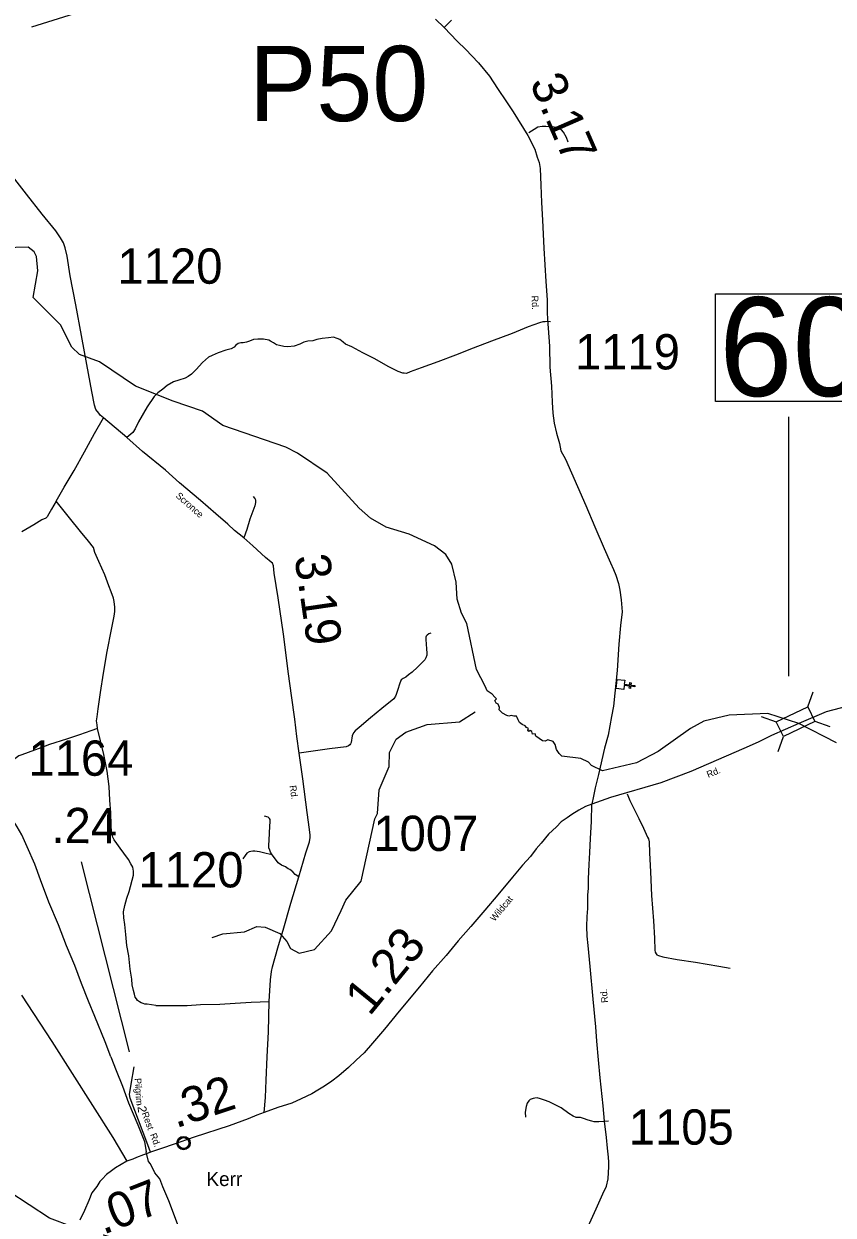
# Model space of a CAD drawing. Extents: x 2093524 to 2270757, y 289120 to 570408.
# Drawn here: x 2214080 to 2225547, y 329610 to 346501 of the extents above; entities that cross this region are included whole.
import ezdxf

# ---------------------------------------------------------------- set-up
doc = ezdxf.new("R2010")
doc.units = 0
for name, color, linetype in [('Exist Civil Demographics Community CELL', 7, 'Continuous'), ('Exist Civil Demographics Community Label', 7, 'Continuous'), ('Exist Cultural Church CELL', 7, 'Continuous'), ('Exist Hydrographic Creek Single Shore', 7, 'Continuous'), ('Exist Hydrographic Misc Water Feature', 7, 'Continuous'), ('Exist Road Non-System Type 51', 7, 'Continuous'), ('Exist Road Secondary Mileage Hundredths English Label', 7, 'Continuous'), ('Exist Road Secondary Structure Pipe Number Label', 7, 'Continuous'), ('Exist Road Secondary Structure Standard Bridge CELL', 7, 'Continuous'), ('Exist Road Secondary Structure Standard Bridge Number Label', 7, 'Continuous'), ('Exist Road Secondary Type 51 Attributed', 7, 'Continuous'), ('Exist Road Secondary Type 51 Label', 7, 'Continuous'), ('Exist Road Secondary Type 51 Number Label', 7, 'Continuous'), ('Exist Utilities Telephone Line', 7, 'Continuous')]:
    doc.layers.add(name, color=color, linetype=linetype)

msp = doc.modelspace()

# ---------------------------------------------------------------- linework, layer by layer
at = {"layer": 'Exist Civil Demographics Community CELL'}
msp.add_lwpolyline([(2216302, 330567), (2216297, 330570), (2216292, 330574), (2216286, 330579), (2216282, 330584), (2216278, 330590), (2216275, 330595), (2216272, 330600), (2216270, 330606), (2216268, 330613), (2216267, 330620), (2216266, 330625), (2216265, 330631), (2216266, 330637), (2216266, 330643), (2216267, 330647), (2216268, 330652), (2216269, 330656), (2216271, 330662), (2216273, 330666), (2216275, 330671), (2216278, 330675), (2216281, 330679), (2216284, 330684), (2216288, 330688), (2216293, 330693), (2216299, 330697), (2216304, 330700), (2216310, 330703), (2216314, 330705), (2216320, 330707), (2216325, 330709), (2216331, 330710), (2216337, 330711), (2216342, 330711), (2216348, 330711), (2216353, 330711), (2216358, 330710), (2216364, 330709), (2216368, 330707), (2216374, 330705), (2216379, 330703), (2216384, 330700), (2216389, 330697), (2216394, 330693), (2216399, 330689), (2216402, 330685), (2216407, 330680), (2216410, 330675), (2216413, 330670), (2216416, 330664), (2216418, 330657), (2216420, 330651), (2216421, 330645), (2216422, 330640), (2216422, 330632), (2216422, 330625), (2216421, 330619), (2216420, 330612), (2216418, 330608), (2216417, 330604), (2216415, 330599), (2216413, 330595), (2216410, 330590), (2216406, 330585), (2216403, 330581), (2216400, 330577), (2216396, 330574), (2216392, 330571), (2216386, 330566), (2216380, 330563), (2216374, 330560), (2216368, 330558), (2216363, 330557), (2216358, 330555), (2216349, 330554), (2216346, 330554), (2216341, 330554), (2216333, 330555), (2216326, 330556), (2216321, 330558), (2216315, 330560), (2216310, 330562), (2216305, 330565)], close=True, dxfattribs=at)
for radius in [94.3, 76.7]:
    msp.add_circle((2216343, 330633), radius, dxfattribs=at)
at = {"layer": 'Exist Cultural Church CELL'}
msp.add_lwpolyline([(2222595, 337194), (2222588, 337137), (2222664, 337128), (2222668, 337160), (2222683, 337158), (2222680, 337126), (2222739, 337119), (2222737, 337103), (2222678, 337110), (2222674, 337079), (2222658, 337081), (2222662, 337112), (2222586, 337121), (2222579, 337064), (2222474, 337077), (2222489, 337206)], close=True, dxfattribs=at)
at = {"layer": 'Exist Hydrographic Creek Single Shore'}
for points in [[(2214140, 343335), (2213965, 343332), (2213807, 343290), (2213541, 343157)], [(2220815, 336777), (2220821, 336808), (2220799, 336857), (2220771, 336868), (2220755, 336908), (2220775, 336932), (2220755, 336952), (2220715, 336998), (2220646, 337043), (2220615, 337109), (2220495, 337348), (2220358, 337997), (2220282, 338146), (2220222, 338344), (2220204, 338587), (2220144, 338838), (2220059, 338977), (2219900, 339102), (2219541, 339266), (2219215, 339364), (2218990, 339494), (2218830, 339634), (2218377, 340132), (2217959, 340413), (2217791, 340501), (2216898, 340804), (2216613, 341010), (2216196, 341149), (2215661, 341363), (2215151, 341708), (2214867, 341815), (2214758, 341916), (2214598, 342231), (2214212, 342619), (2214276, 343001), (2214258, 343202), (2214224, 343268), (2214140, 343335)], [(2222279, 335912), (2222125, 335987), (2222079, 336032), (2221974, 336087), (2221702, 336118), (2221664, 336158), (2221627, 336213), (2221607, 336282), (2221582, 336327), (2221504, 336349), (2221467, 336329), (2221427, 336333), (2221334, 336400), (2221323, 336433), (2221289, 336429), (2221278, 336468), (2221254, 336484), (2221234, 336468), (2221223, 336488), (2221232, 336508), (2221203, 336524), (2221183, 336548), (2221143, 336568), (2221103, 336593), (2221083, 336633), (2221072, 336664), (2221059, 336684), (2221023, 336684), (2220983, 336695), (2220953, 336684), (2220923, 336693), (2220862, 336728), (2220815, 336777)], [(2224623, 336725), (2224073, 336697), (2223716, 336612), (2223525, 336511), (2223069, 336182), (2222762, 336021), (2222279, 335912)], [(2225594, 336309), (2225059, 336582), (2224623, 336725)]]:
    msp.add_lwpolyline(points, dxfattribs=at)
at = {"layer": 'Exist Hydrographic Misc Water Feature'}
for points in [[(2214194, 346460), (2215099, 346741), (2215481, 346986), (2215664, 347045)], [(2216748, 333548), (2216898, 333598), (2217206, 333628), (2217380, 333703), (2217497, 333694), (2217706, 333605), (2217806, 333488), (2217857, 333389), (2217983, 333324), (2218199, 333375), (2218438, 333643), (2218578, 333929), (2218644, 334078), (2218858, 334346), (2219052, 335231), (2219093, 335306), (2219116, 335640), (2219255, 335972), (2219262, 336172), (2219353, 336357), (2219494, 336459), (2219793, 336568), (2220251, 336605), (2220475, 336748)], [(2215806, 328817), (2215404, 329242), (2215278, 329307), (2214769, 329445), (2214443, 329566), (2213866, 329948), (2213640, 330054), (2213356, 330250), (2213020, 330608), (2212694, 330745), (2212560, 330853), (2212375, 331184), (2212366, 331260), (2212230, 331584), (2212155, 331684), (2211611, 331954)]]:
    msp.add_lwpolyline(points, dxfattribs=at)
at = {"layer": 'Exist Road Non-System Type 51'}
for points in [[(2220139, 346555), (2220035, 346451)], [(2221794, 344823), (2221768, 344888), (2221725, 344964), (2221699, 344996), (2221667, 345018), (2221627, 345031), (2221559, 345041), (2221477, 345046), (2221423, 345046), (2221363, 345036), (2221311, 345005), (2221236, 344955)], [(2221544, 342274), (2221496, 342282), (2221468, 342277), (2221432, 342277), (2221386, 342261), (2221227, 342204), (2220999, 342112), (2220708, 342002), (2220447, 341903), (2220194, 341803), (2219947, 341711), (2219709, 341623), (2219556, 341566), (2219504, 341544), (2219468, 341546), (2219448, 341548), (2219384, 341573), (2219241, 341642), (2219051, 341749), (2218884, 341838), (2218726, 341919), (2218639, 341958), (2218603, 341988), (2218557, 342027), (2218517, 342041), (2218467, 342057), (2218397, 342050), (2218305, 342038), (2218233, 342023), (2218173, 342005), (2218105, 342002), (2218048, 341986), (2217988, 341957), (2217908, 341933), (2217820, 341922), (2217762, 341924), (2217700, 341939), (2217658, 341949), (2217616, 341977), (2217576, 342003), (2217550, 342018), (2217474, 342028), (2217397, 342031), (2217333, 342023), (2217276, 342000), (2217236, 341986), (2217186, 341976), (2217154, 341978), (2217118, 341967), (2217082, 341943), (2217060, 341917), (2217019, 341895), (2216943, 341874), (2216835, 341836), (2216747, 341797), (2216697, 341773), (2216612, 341700), (2216523, 341601), (2216455, 341533), (2216410, 341499), (2216366, 341479), (2216278, 341450), (2216198, 341425), (2216109, 341375), (2216049, 341322), (2215977, 341268), (2215926, 341218), (2215829, 341069), (2215704, 340858), (2215657, 340760), (2215623, 340706), (2215540, 340637)], [(2214538, 339732), (2214651, 339931), (2214793, 340170), (2214939, 340435), (2215083, 340694), (2215208, 340917)], [(2214538, 339732), (2214471, 339622), (2214434, 339552), (2214408, 339512), (2214390, 339492), (2214336, 339467), (2214221, 339398), (2214050, 339299)], [(2215124, 336510), (2215118, 336564), (2215108, 336620), (2215117, 336676), (2215132, 336790), (2215165, 337022), (2215207, 337294), (2215259, 337602), (2215323, 337916), (2215361, 338105), (2215367, 338167), (2215368, 338229), (2215358, 338311), (2215348, 338356), (2215315, 338448), (2215286, 338534), (2215225, 338688), (2215142, 338877), (2215087, 339005), (2215067, 339074), (2214998, 339166), (2214883, 339303), (2214726, 339496), (2214538, 339732)], [(2217327, 339798), (2217347, 339778), (2217357, 339764), (2217363, 339744), (2217363, 339714), (2217354, 339668), (2217283, 339476), (2217238, 339331), (2217195, 339213)], [(2219847, 337864), (2219817, 337854), (2219795, 337833), (2219782, 337821), (2219775, 337807), (2219776, 337769), (2219782, 337711), (2219787, 337633), (2219789, 337583), (2219789, 337550), (2219776, 337513), (2219760, 337485), (2219726, 337447), (2219658, 337381), (2219581, 337310), (2219529, 337270), (2219493, 337239), (2219456, 337217), (2219428, 337199), (2219406, 337153), (2219373, 337051), (2219357, 336993), (2219348, 336969), (2219320, 336932), (2219151, 336795), (2218990, 336660), (2218831, 336523), (2218775, 336479), (2218751, 336451), (2218732, 336407), (2218718, 336311), (2218710, 336295), (2218700, 336278), (2218679, 336262), (2218647, 336252), (2218411, 336220), (2217982, 336162)], [(2215124, 336510), (2215027, 336475), (2214867, 336420), (2214684, 336359), (2214442, 336281), (2214283, 336224), (2214141, 336171), (2214049, 336138), (2214007, 336124), (2213910, 336046), (2213872, 336019), (2213781, 335965), (2213669, 335910)], [(2215951, 332585), (2215887, 332590), (2215829, 332600), (2215795, 332604), (2215769, 332612), (2215743, 332621), (2215717, 332633), (2215691, 332653), (2215678, 332679), (2215656, 332703), (2215646, 332745), (2215632, 332797), (2215615, 332878), (2215611, 332958), (2215586, 333098), (2215566, 333286), (2215541, 333434), (2215524, 333591), (2215509, 333733), (2215497, 333825), (2215492, 333909), (2215512, 334001), (2215541, 334105), (2215572, 334198), (2215632, 334432), (2215634, 334486), (2215624, 334544), (2215597, 334590), (2215563, 334653), (2215498, 334741), (2215446, 334815), (2215397, 334882), (2215359, 334930), (2215339, 334970), (2215322, 335046), (2215316, 335138), (2215313, 335315), (2215297, 335495), (2215288, 335687), (2215258, 335905), (2215215, 336143), (2215166, 336334), (2215124, 336510)], [(2222628, 335582), (2222666, 335488), (2222727, 335368), (2222794, 335233), (2222861, 335099), (2222899, 335014), (2222918, 334970), (2222930, 334944), (2222938, 334902), (2222945, 334746), (2222959, 334478), (2222975, 334141), (2223000, 333783), (2223016, 333537), (2223021, 333367), (2223027, 333339), (2223041, 333315), (2223051, 333301), (2223073, 333290), (2223135, 333272), (2223338, 333237), (2223598, 333195), (2223928, 333142), (2224088, 333111)], [(2217598, 334721), (2217577, 334757), (2217563, 334787), (2217553, 334817), (2217553, 334859), (2217554, 334923), (2217560, 335029), (2217565, 335123), (2217570, 335191), (2217570, 335219), (2217562, 335235), (2217540, 335251), (2217488, 335269)], [(2217598, 334721), (2217512, 334737), (2217419, 334760), (2217351, 334772), (2217325, 334773), (2217297, 334767), (2217274, 334761), (2217238, 334743), (2217214, 334711), (2217182, 334660)], [(2217974, 334408), (2217925, 334440), (2217891, 334476), (2217849, 334509), (2217827, 334521), (2217789, 334549), (2217731, 334574), (2217684, 334604), (2217646, 334658), (2217598, 334721)], [(2215951, 332585), (2216041, 332585), (2216211, 332582), (2216393, 332584), (2216585, 332595), (2216857, 332603), (2217072, 332614), (2217302, 332630), (2217558, 332640)], [(2222362, 330944), (2222292, 330939), (2222228, 330935), (2222184, 330932), (2222160, 330934), (2222130, 330942), (2222078, 330958), (2222012, 330981), (2221967, 330995), (2221948, 330997), (2221906, 330996), (2221865, 331012), (2221801, 331050), (2221695, 331131), (2221616, 331172), (2221522, 331218), (2221456, 331243), (2221402, 331261), (2221354, 331275), (2221320, 331270), (2221296, 331264), (2221256, 331248), (2221236, 331232), (2221212, 331200), (2221199, 331151), (2221185, 331071), (2221188, 330998)]]:
    msp.add_lwpolyline(points, dxfattribs=at)
at = {"layer": 'Exist Road Secondary Structure Standard Bridge CELL'}
for p, q in [((2225189, 336818), (2225264, 337031)), ((2224528, 336679), (2224742, 336604)), ((2225287, 336614), (2225501, 336539)), ((2224767, 336182), (2224842, 336395))]:
    msp.add_line(p, q, dxfattribs=at)
msp.add_lwpolyline([(2224742, 336604), (2225189, 336819), (2225289, 336610), (2224842, 336395)], close=True, dxfattribs=at)
at = {"layer": 'Exist Road Secondary Structure Standard Bridge Number Label'}
msp.add_line((2224920, 337254), (2224920, 340931), dxfattribs=at)
msp.add_lwpolyline([(2223881, 342674), (2226458, 342674), (2226458, 341145), (2223881, 341145)], close=True, dxfattribs=at)
at = {"layer": 'Exist Road Secondary Type 51 Attributed'}
for points in [[(2219915, 346568), (2220035, 346451), (2220219, 346256), (2220342, 346136), (2220427, 346047), (2220520, 345947), (2220677, 345761), (2220793, 345586), (2220917, 345395), (2221014, 345251), (2221223, 344919), (2221320, 344724), (2221354, 344610), (2221380, 344535), (2221394, 344448), (2221405, 344214), (2221414, 343969), (2221431, 343719), (2221447, 343318), (2221476, 342848), (2221494, 342588), (2221493, 342408), (2221502, 342315), (2221527, 341930), (2221531, 341635), (2221555, 341364), (2221567, 341136), (2221573, 340979), (2221593, 340839), (2221626, 340695), (2221668, 340553), (2221689, 340449), (2221755, 340329), (2221926, 339939), (2222041, 339673), (2222170, 339367), (2222301, 339063), (2222394, 338857), (2222436, 338766), (2222467, 338686), (2222507, 338566), (2222524, 338471), (2222544, 338336), (2222556, 338165), (2222533, 337970), (2222509, 337704), (2222485, 337331), (2222454, 337010), (2222433, 336828), (2222407, 336679), (2222358, 336417), (2222307, 336229), (2222223, 335856), (2222176, 335667), (2222151, 335551), (2222130, 335435)], [(2217486, 331064), (2217503, 331280), (2217512, 331526), (2217527, 331854), (2217547, 332208), (2217558, 332640), (2217576, 332948), (2217587, 333066), (2217605, 333132), (2217636, 333250), (2217688, 333435), (2217753, 333651), (2217864, 334034), (2217974, 334408), (2218075, 334745), (2218126, 334901), (2218136, 334965), (2218135, 334999), (2218125, 335077), (2218093, 335321), (2218034, 335796), (2217982, 336162), (2217950, 336397), (2217920, 336641), (2217874, 336979), (2217830, 337286), (2217758, 337847), (2217683, 338365), (2217626, 338712), (2217618, 338818), (2217603, 338852), (2217583, 338868), (2217505, 338933), (2217324, 339098), (2217195, 339213), (2217066, 339316), (2216968, 339407), (2216801, 339552), (2216582, 339745), (2216286, 339994), (2216085, 340173), (2215763, 340439), (2215540, 340637), (2215208, 340917), (2215162, 340954), (2215140, 340982), (2215099, 341032), (2215079, 341096), (2215043, 341289), (2214971, 341671), (2214896, 342084), (2214817, 342517), (2214738, 342927), (2214693, 343206), (2214666, 343326), (2214643, 343396), (2214601, 343466), (2214532, 343565), (2214337, 343802), (2214115, 344086), (2213852, 344424)], [(2230785, 337533), (2230560, 337489), (2230207, 337437), (2229725, 337437), (2229443, 337474), (2228390, 337508), (2228268, 337491), (2227458, 337285), (2226095, 336925), (2225843, 336850), (2225450, 336747), (2225059, 336582)], [(2225059, 336582), (2224676, 336413), (2224483, 336318), (2224281, 336227), (2223531, 335900), (2223104, 335739), (2222391, 335532), (2222130, 335435)], [(2222130, 335435), (2222039, 335403), (2221945, 335352), (2221844, 335291), (2221776, 335244), (2221695, 335186), (2221625, 335115), (2221516, 335010), (2221410, 334883), (2221337, 334802), (2221258, 334695), (2221145, 334574), (2221004, 334403), (2220794, 334154), (2220613, 333936), (2220413, 333705), (2220235, 333501), (2220063, 333291), (2219872, 333074), (2219684, 332848), (2219396, 332501), (2219192, 332246), (2219022, 332051), (2218900, 331913), (2218787, 331810), (2218679, 331705), (2218542, 331585), (2218444, 331508), (2218340, 331439), (2218246, 331382), (2218159, 331330), (2218007, 331258), (2217879, 331200), (2217677, 331135), (2217486, 331064)], [(2222073, 329440), (2222189, 329699), (2222286, 329911), (2222335, 330021), (2222358, 330125), (2222362, 330216), (2222368, 330297), (2222368, 330361), (2222364, 330432), (2222350, 330560), (2222336, 330712), (2222308, 330942), (2222289, 331161), (2222248, 331559), (2222224, 331812), (2222199, 332076), (2222184, 332281), (2222148, 332673), (2222103, 333134), (2222074, 333435), (2222060, 333567), (2222055, 333701), (2222061, 333843), (2222071, 333957), (2222073, 334153), (2222079, 334242), (2222082, 334377), (2222090, 334582), (2222098, 334750), (2222107, 334950), (2222125, 335191), (2222130, 335435)], [(2214045, 332729), (2214475, 332071), (2215340, 330711), (2215541, 330376)], [(2215875, 330503), (2215836, 330606), (2215769, 330780), (2215586, 331268), (2215576, 331320), (2215599, 331469), (2215643, 331714)], [(2217486, 331064), (2217383, 331027), (2217258, 330978), (2216989, 330879), (2216494, 330714), (2216195, 330612), (2216044, 330560), (2215875, 330503)], [(2215875, 330503), (2215843, 330489), (2215774, 330466), (2215675, 330427), (2215623, 330404), (2215541, 330376)], [(2215541, 330376), (2215379, 330282), (2215322, 330240), (2215253, 330185), (2215190, 330121), (2215156, 330089), (2215116, 330015), (2215041, 329926), (2215002, 329817), (2214938, 329678), (2214873, 329540)]]:
    msp.add_lwpolyline(points, dxfattribs=at)
at = {"layer": 'Exist Road Secondary Type 51 Number Label'}
msp.add_line((2215578, 331925), (2214895, 334621), dxfattribs=at)
at = {"layer": 'Exist Utilities Telephone Line'}
for points in [[(2215312, 331853), (2215233, 332068), (2215084, 332425), (2214995, 332642), (2214897, 332897), (2214802, 333149), (2214684, 333430), (2214570, 333725), (2214434, 334050), (2214316, 334363), (2214234, 334588), (2214126, 334831), (2214049, 335001), (2213984, 335116), (2213891, 335266), (2213766, 335449), (2213589, 335671), (2213391, 335930), (2213161, 336240), (2212953, 336513), (2212729, 336785), (2212520, 337071), (2212310, 337334), (2212074, 337638)], [(2215312, 331853), (2215388, 331663), (2215479, 331438), (2215563, 331203), (2215693, 330892), (2215790, 330656), (2215814, 330508)], [(2218307, 324330), (2218146, 324731), (2217902, 325333), (2217617, 326047), (2217377, 326679), (2217088, 327386), (2216858, 327979), (2216653, 328499), (2216441, 329015), (2216283, 329410), (2216134, 329813), (2216051, 330012), (2216008, 330124), (2215935, 330212), (2215872, 330337), (2215846, 330373), (2215814, 330508)]]:
    msp.add_lwpolyline(points, dxfattribs=at)

# ---------------------------------------------------------------- texts
at = {"layer": 'Exist Civil Demographics Community Label'}
msp.add_text('Kerr', height=200, dxfattribs=at).set_placement((2216668, 330023))
at = {"layer": 'Exist Road Secondary Mileage Hundredths English Label'}
for s, height, rotation, p in [('3.17', 500, 293.6031, (2221241, 345669)), ('3.19', 500, 278.3063, (2217912, 338949)), ('.24', 500, 359.9262, (2214470, 334885)), ('1.23', 500, 50.8156, (2218978, 332418)), ('.32', 500, 18.4349, (2216233, 330840)), ('.2', 125, 278.2024, (2215682, 331194)), ('.07', 500, 21.4477, (2215205, 329329))]:
    msp.add_text(s, height=height, rotation=rotation, dxfattribs=at).set_placement(p)
at = {"layer": 'Exist Road Secondary Structure Pipe Number Label'}
msp.add_text('P50', height=1066.3, dxfattribs=at).set_placement((2217273, 345122))
at = {"layer": 'Exist Road Secondary Structure Standard Bridge Number Label'}
msp.add_text('60', height=1400, dxfattribs=at).set_placement((2223931, 341224))
at = {"layer": 'Exist Road Secondary Type 51 Label'}
for s, rotation, p in [('Rd.', 272.9369, (2221272, 342645)), ('Scronce', 318.7025, (2216224, 339797)), ('Rd.', 21.9747, (2223778, 335809)), ('Rd.', 277.8088, (2217844, 335698)), ('Wildcat', 50.2379, (2220750, 333767)), ('Rd.', 95.8363, (2222360, 332625)), ('Pilgrim', 273.7063, (2215648, 331550)), ('Rest', 290.2731, (2215748, 331055)), ('Rd.', 290.8636, (2215865, 330752))]:
    msp.add_text(s, height=95, rotation=rotation, dxfattribs=at).set_placement(p)
at = {"layer": 'Exist Road Secondary Type 51 Number Label'}
for s, p in [('1120', (2215407, 342816)), ('1119', (2221889, 341601)), ('1164', (2214145, 335840)), ('1007', (2219032, 334774)), ('1120', (2215705, 334257)), ('1105', (2222652, 330610))]:
    msp.add_text(s, height=500, dxfattribs=at).set_placement(p)

doc.saveas('drawing.dxf')
